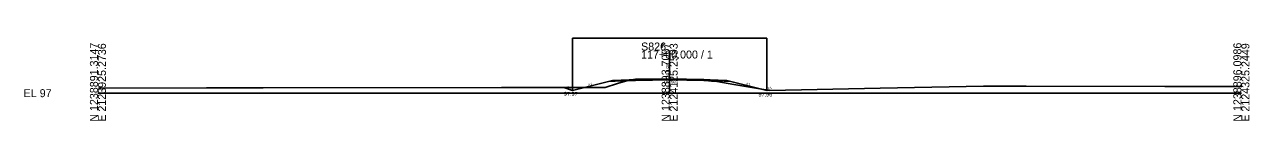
# Model space of a CAD drawing. Extents: x 2119282 to 2119710, y 1215030 to 1220057.
# Drawn here: x 2119281.9 to 2119710.4, y 1215530.1 to 1215559.1 of the extents above; entities that cross this region are included whole.
import ezdxf

# ---------------------------------------------------------------- set-up
doc = ezdxf.new("R2010")
doc.units = 0
for name, color, linetype in [('XS_CELL', 7, 'Continuous'), ('XS_M_DITCH', 7, 'Continuous'), ('XS_P_FINISHED_GRADE', 7, 'Continuous'), ('XS_P_FINISHED_GRADE_ELEV_TX', 7, 'Continuous'), ('XS_P_SUBGRADE_GRANULAR', 7, 'Continuous'), ('XS_P_SUBGRADE_PAVEMENT', 7, 'Continuous'), ('XS_P_TX_DCH', 7, 'Continuous'), ('XS_P_TX_FS_BS', 7, 'Continuous'), ('XS_X_GROUND', 7, 'Continuous'), ('XS_X_GROUND_TX', 7, 'Continuous')]:
    doc.layers.add(name, color=color, linetype=linetype)

msp = doc.modelspace()

# ---------------------------------------------------------------- linework, layer by layer
at = {"layer": 'XS_CELL'}
for p, q in [((2119507.6, 1215539.8), (2119507.6, 1215554.74)), ((2119307.6, 1215539.8), (2119507.6, 1215539.8)), ((2119507.6, 1215539.8), (2119707.6, 1215539.8))]:
    msp.add_line(p, q, dxfattribs=at)
at = {"layer": 'XS_M_DITCH'}
for p, q in [((2119473.6, 1215540.77), (2119473.6, 1215559.07)), ((2119473.6, 1215559.07), (2119541.6, 1215559.07)), ((2119541.6, 1215540.76), (2119541.6, 1215559.07))]:
    msp.add_line(p, q, dxfattribs=at)
at = {"layer": 'XS_P_FINISHED_GRADE'}
for p, q in [((2119473.6, 1215540.77), (2119470.6, 1215541.77)), ((2119487.6, 1215544.26), (2119473.6, 1215540.77)), ((2119493.6, 1215544.5), (2119487.6, 1215544.26)), ((2119495.6, 1215544.54), (2119493.6, 1215544.5)), ((2119507.6, 1215544.78), (2119495.6, 1215544.54)), ((2119507.6, 1215544.78), (2119519.6, 1215544.54)), ((2119519.6, 1215544.54), (2119521.6, 1215544.5)), ((2119521.6, 1215544.5), (2119527.6, 1215544.26)), ((2119527.6, 1215544.26), (2119541.6, 1215540.76)), ((2119541.6, 1215540.76), (2119541.9, 1215540.86))]:
    msp.add_line(p, q, dxfattribs=at)
at = {"layer": 'XS_P_SUBGRADE_GRANULAR'}
for p, q in [((2119493.17, 1215544.2), (2119486.25, 1215543.93)), ((2119522.04, 1215544.2), (2119528.95, 1215543.93))]:
    msp.add_line(p, q, dxfattribs=at)
at = {"layer": 'XS_P_SUBGRADE_PAVEMENT'}
for p, q in [((2119493.6, 1215544.5), (2119493.17, 1215544.2)), ((2119495.61, 1215544.25), (2119493.17, 1215544.2)), ((2119507.6, 1215544.49), (2119495.61, 1215544.25)), ((2119507.6, 1215544.49), (2119519.6, 1215544.25)), ((2119519.6, 1215544.25), (2119522.04, 1215544.2)), ((2119521.6, 1215544.5), (2119522.04, 1215544.2))]:
    msp.add_line(p, q, dxfattribs=at)
at = {"layer": 'XS_X_GROUND'}
for p, q in [((2119307.75, 1215541.54), (2119345.55, 1215541.61)), ((2119345.55, 1215541.61), (2119365.43, 1215541.62)), ((2119365.43, 1215541.62), (2119448.78, 1215541.74)), ((2119448.78, 1215541.74), (2119461.55, 1215541.76)), ((2119461.55, 1215541.76), (2119466.09, 1215541.77)), ((2119466.09, 1215541.77), (2119485.01, 1215541.75)), ((2119485.01, 1215541.75), (2119489.38, 1215543.2)), ((2119489.38, 1215543.2), (2119493.82, 1215544.49)), ((2119493.82, 1215544.49), (2119494.93, 1215544.62)), ((2119494.93, 1215544.62), (2119495.69, 1215544.68)), ((2119495.69, 1215544.68), (2119503.25, 1215544.73)), ((2119503.25, 1215544.73), (2119507.6, 1215544.78)), ((2119507.6, 1215544.78), (2119511.93, 1215544.61)), ((2119511.93, 1215544.61), (2119518.98, 1215544.38)), ((2119518.98, 1215544.38), (2119522.29, 1215544.05)), ((2119522.29, 1215544.05), (2119524.14, 1215543.9)), ((2119524.14, 1215543.9), (2119530.1, 1215542.86)), ((2119530.1, 1215542.86), (2119542.6, 1215540.74)), ((2119542.6, 1215540.74), (2119581.19, 1215541.55)), ((2119581.19, 1215541.55), (2119617.4, 1215542.23)), ((2119617.4, 1215542.23), (2119632.26, 1215542.23)), ((2119632.26, 1215542.23), (2119680.85, 1215542.19)), ((2119680.85, 1215542.19), (2119705.37, 1215542.15)), ((2119705.37, 1215542.15), (2119707.75, 1215542.13))]:
    msp.add_line(p, q, dxfattribs=at)

# ---------------------------------------------------------------- texts
at = {"layer": 'XS_CELL'}
for s, p in [('N 1238891.3147', (2119307.6, 1215529.8)), ('E 2123925.2736', (2119310.4, 1215529.8)), ('N 1238893.7067', (2119507.6, 1215529.8)), ('E 2124125.2593', (2119510.4, 1215529.8)), ('N 1238896.0986', (2119707.6, 1215529.8)), ('E 2124325.2449', (2119710.4, 1215529.8))]:
    msp.add_text(s, height=2.8, rotation=90, dxfattribs=at).set_placement(p)
for s, p in [('S826', (2119497.6, 1215554.74)), ('117+00.000 / 1', (2119497.6, 1215551.94)), ('EL 97', (2119281.6, 1215538.4))]:
    msp.add_text(s, height=2.8, dxfattribs=at).set_placement(p)
at = {"layer": 'XS_P_FINISHED_GRADE_ELEV_TX'}
msp.add_text('101.98', height=1.25, rotation=90, dxfattribs=at).set_placement((2119507.6, 1215545.02))
at = {"layer": 'XS_P_TX_DCH'}
for s, p in [('97.97', (2119470.59, 1215538.86)), ('97.96', (2119538.66, 1215538.61))]:
    msp.add_text(s, height=1.4, dxfattribs=at).set_placement(p)
at = {"layer": 'XS_P_TX_FS_BS'}
for s, rotation, p in [('3:1', 341.5921, (2119471.67, 1215541.53)), ('4:1', 14.015, (2119479.11, 1215542.38)), ('4:1', 345.9638, (2119534.27, 1215542.75)), ('3:1', 18.4349, (2119541.97, 1215540.94))]:
    msp.add_text(s, height=0.8, rotation=rotation, dxfattribs=at).set_placement(p)
at = {"layer": 'XS_X_GROUND_TX'}
msp.add_text('101.98', height=1, dxfattribs=at).set_placement((2119505.47, 1215543.12))

doc.saveas('drawing.dxf')
